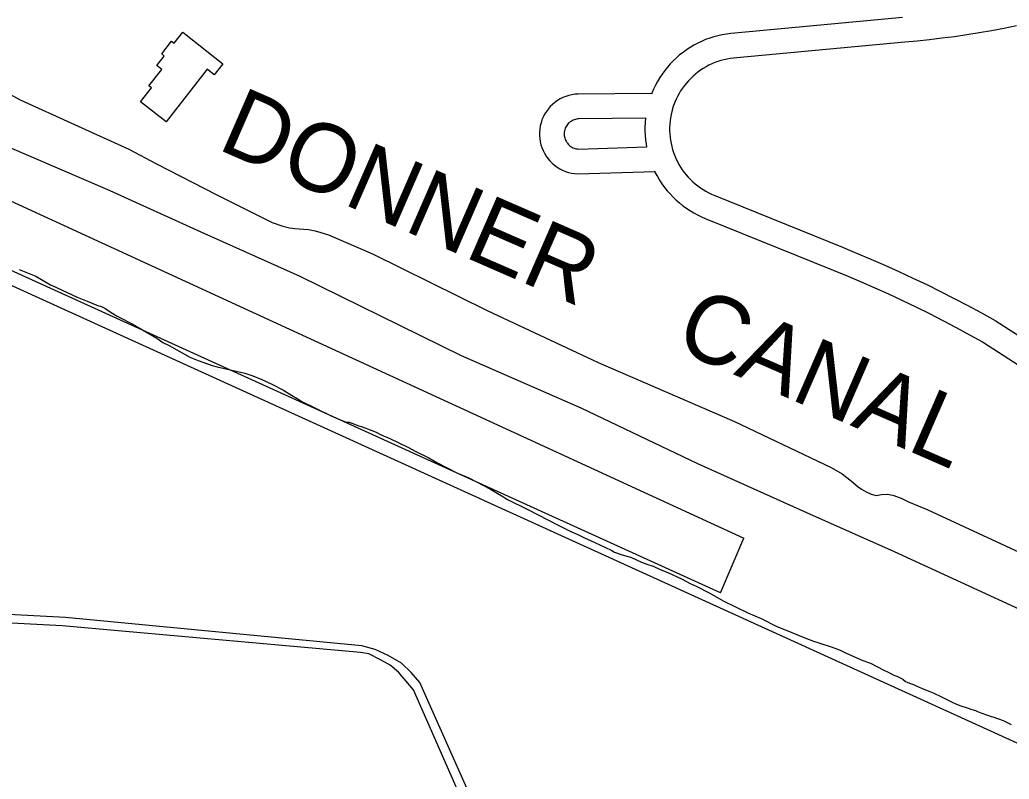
# Model space of a CAD drawing. Extents: x 3715084 to 3753216, y 488173 to 513963.
# Drawn here: x 3720571 to 3721771, y 509921 to 510842 of the extents above; entities that cross this region are included whole.
import ezdxf

# ---------------------------------------------------------------- set-up
doc = ezdxf.new("R2010")
doc.units = 0
for name, color, linetype in [('V-BLDG-OTLN', 7, 'Continuous'), ('V-LEVE-TOET', 7, 'Continuous'), ('V-RIVR-IDEN', 7, 'Continuous'), ('V-ROAD-CNTR', 7, 'Continuous'), ('V-SITE-VEGE', 7, 'Continuous'), ('V-TOPO-BNDY', 7, 'Continuous'), ('V-TOPO-SHOR', 7, 'Continuous')]:
    doc.layers.add(name, color=color, linetype=linetype)

msp = doc.modelspace()

# ---------------------------------------------------------------- linework, layer by layer
at = {"layer": 'V-BLDG-OTLN'}
msp.add_lwpolyline([(3720768.4, 510826.9), (3720817.2, 510788.8), (3720806.7, 510775.3), (3720798.2, 510782), (3720748.3, 510718.1), (3720717.2, 510742.4), (3720730.6, 510759.6), (3720727.4, 510762.1), (3720742.9, 510781.9), (3720736.9, 510786.5), (3720746, 510798.1), (3720742.9, 510800.6), (3720754.9, 510816), (3720758, 510813.6)], close=True, dxfattribs=at)
at = {"layer": 'V-LEVE-TOET'}
msp.add_line((3721421.2, 510147.1), (3721449.3, 510213.4), dxfattribs=at)
for points in [[(3719136.8, 511278.1), (3720138.4, 510815.9), (3721449.3, 510213.4)], [(3721421.2, 510147.1), (3719137.9, 511184.1)]]:
    msp.add_lwpolyline(points, dxfattribs=at)
at = {"layer": 'V-ROAD-CNTR'}
for points in [[(3721641.9, 510844.8), (3721438.4, 510825.9), (3721433.5, 510825.5), (3721428.3, 510824.8), (3721423.2, 510823.9), (3721418, 510822.8), (3721413, 510821.4), (3721408, 510819.8), (3721403, 510818), (3721398.2, 510815.9), (3721393.5, 510813.7), (3721388.8, 510811.2), (3721384.3, 510808.5), (3721379.9, 510805.7), (3721375.7, 510802.6), (3721371.5, 510799.4), (3721367.6, 510795.9), (3721363.8, 510792.3), (3721360.1, 510788.5), (3721356.6, 510784.6), (3721353.4, 510780.5), (3721350.3, 510776.3), (3721347.3, 510771.9), (3721344.6, 510767.4), (3721342.1, 510762.8), (3721339.8, 510758), (3721337.8, 510753.2), (3721337.3, 510752)], [(3721780.3, 510834.6), (3721765, 510831.5), (3721750, 510828.7), (3721735, 510826.1), (3721720, 510823.7), (3721704.9, 510821.5), (3721689.9, 510819.6), (3721674.7, 510817.8), (3721659.6, 510816.3), (3721644.6, 510815), (3721441, 510796), (3721436.7, 510795.6), (3721432.9, 510795.1), (3721429, 510794.5), (3721425.2, 510793.6), (3721421.4, 510792.6), (3721417.7, 510791.4), (3721414.1, 510790.1), (3721410.5, 510788.5), (3721407, 510786.9), (3721403.5, 510785), (3721400.2, 510783.1), (3721396.9, 510780.9), (3721393.7, 510778.6), (3721390.7, 510776.2), (3721387.7, 510773.7), (3721384.9, 510771), (3721382.2, 510768.2), (3721379.6, 510765.3), (3721377.2, 510762.2), (3721374.9, 510759.1), (3721372.7, 510755.8), (3721370.7, 510752.5), (3721368.8, 510749.1), (3721367.1, 510745.6), (3721365.6, 510742), (3721364.2, 510738.3), (3721363, 510734.6), (3721362.7, 510733.7), (3721361.9, 510730.9), (3721361.1, 510727.1), (3721360.4, 510723.2), (3721359.8, 510719.4), (3721359.5, 510715.5), (3721359.3, 510711.6), (3721359.3, 510707.7), (3721359.4, 510703.8), (3721359.8, 510699.9), (3721360.3, 510696), (3721361, 510692.2), (3721361.9, 510688.4), (3721362.9, 510684.6), (3721364.1, 510680.9), (3721364.9, 510678.7), (3721365.5, 510677.3), (3721367, 510673.7), (3721368.7, 510670.2), (3721370.5, 510666.7), (3721372.5, 510663.4), (3721374.7, 510660.1), (3721377, 510657), (3721379.4, 510653.9), (3721382, 510651), (3721384.7, 510648.2), (3721387.5, 510645.5), (3721390.4, 510642.9), (3721393.5, 510640.5), (3721396.6, 510638.2), (3721399.9, 510636.1), (3721403.2, 510634.1), (3721406.7, 510632.2), (3721410.2, 510630.5), (3721414, 510628.9), (3721569.1, 510566.2), (3721586.3, 510559.1), (3721603.5, 510551.9), (3721620.6, 510544.4), (3721637.6, 510536.7), (3721654.6, 510528.8), (3721671.4, 510520.8), (3721688.2, 510512.5), (3721704.8, 510504), (3721721.3, 510495.3), (3721737.8, 510486.4), (3721754.4, 510477.1), (3721825.5, 510431.5)], [(3721337.6, 510752.7), (3721248.2, 510751.9), (3721244.5, 510751.7), (3721240.7, 510751.1), (3721237, 510750.3), (3721233.4, 510749.2), (3721229.8, 510747.7), (3721226.4, 510746), (3721223.2, 510744.1), (3721220.1, 510741.8), (3721217.1, 510739.4), (3721214.4, 510736.7), (3721211.9, 510733.8), (3721209.7, 510730.8), (3721207.6, 510727.5), (3721205.9, 510724.1), (3721204.4, 510720.6), (3721203.2, 510717), (3721202.3, 510713.3), (3721201.7, 510709.5), (3721201.3, 510705.8), (3721201.3, 510701.9), (3721201.6, 510698.1), (3721202.2, 510694.4), (3721203.1, 510690.6), (3721204.2, 510687), (3721205.7, 510683.5), (3721207.4, 510680.1), (3721209.4, 510676.8), (3721211.6, 510673.7), (3721214.1, 510670.8), (3721216.8, 510668.1), (3721219.7, 510665.6), (3721222.7, 510663.4), (3721226, 510661.4), (3721229.4, 510659.7), (3721232.9, 510658.2), (3721236.6, 510657), (3721240.3, 510656.1), (3721244, 510655.5), (3721248.1, 510655.2), (3721341.2, 510658.2)], [(3721330, 510722.6), (3721249.3, 510722), (3721247.7, 510721.8), (3721246.3, 510721.6), (3721244.9, 510721.3), (3721243.5, 510720.9), (3721242.2, 510720.3), (3721240.9, 510719.7), (3721239.6, 510718.9), (3721238.4, 510718.1), (3721237.3, 510717.2), (3721236.3, 510716.2), (3721235.4, 510715.1), (3721234.5, 510713.9), (3721233.7, 510712.7), (3721233.1, 510711.4), (3721232.5, 510710.1), (3721232, 510708.7), (3721231.7, 510707.3), (3721231.5, 510705.8), (3721231.3, 510704.4), (3721231.3, 510703), (3721231.4, 510701.5), (3721231.7, 510700.1), (3721232, 510698.7), (3721232.4, 510697.3), (3721233, 510696), (3721233.6, 510694.7), (3721234.4, 510693.4), (3721235.2, 510692.3), (3721236.2, 510691.2), (3721237.2, 510690.1), (3721238.3, 510689.2), (3721239.5, 510688.3), (3721240.7, 510687.6), (3721242, 510686.9), (3721243.3, 510686.4), (3721244.7, 510685.9), (3721246.1, 510685.6), (3721247.5, 510685.4), (3721248.7, 510685.3), (3721331.3, 510687.9)], [(3721330.1, 510723.3), (3721330, 510722.8), (3721329.5, 510717.6), (3721329.3, 510712.3), (3721329.3, 510707.1), (3721329.5, 510701.8), (3721330, 510696.6), (3721330.7, 510691.4), (3721331.4, 510687.6)], [(3721340.8, 510658.8), (3721341.9, 510656.6), (3721344.4, 510652), (3721347.1, 510647.4), (3721350, 510643.1), (3721353.1, 510638.8), (3721356.4, 510634.7), (3721359.8, 510630.8), (3721363.5, 510627), (3721367.2, 510623.3), (3721371.2, 510619.9), (3721375.3, 510616.6), (3721379.6, 510613.5), (3721383.9, 510610.6), (3721388.5, 510608), (3721393.1, 510605.5), (3721397.8, 510603.2), (3721402.5, 510601.2), (3721557.8, 510538.4), (3721574.8, 510531.4), (3721591.7, 510524.3), (3721608.5, 510517), (3721625.1, 510509.5), (3721641.8, 510501.7), (3721658.3, 510493.8), (3721674.7, 510485.7), (3721691, 510477.3), (3721707.2, 510468.8), (3721723.3, 510460.1), (3721739, 510451.4), (3721808.8, 510406.6)]]:
    msp.add_lwpolyline(points, dxfattribs=at)
at = {"layer": 'V-SITE-VEGE'}
for p, q in [((3720569.8, 510539.2), (3720589.9, 510530.9)), ((3720589.9, 510530.9), (3720607.8, 510520.5)), ((3720607.8, 510520.5), (3720614.3, 510517.8)), ((3720614.3, 510517.8), (3720621.9, 510513.9)), ((3720621.9, 510513.9), (3720640.3, 510505.7)), ((3720640.3, 510505.7), (3720652.2, 510500.7)), ((3720652.2, 510500.7), (3720666.3, 510495.2)), ((3720666.3, 510495.2), (3720668.5, 510494.7)), ((3720668.5, 510494.7), (3720671.2, 510493.6)), ((3720671.2, 510493.6), (3720675, 510491.4)), ((3720675, 510491.4), (3720681.5, 510487)), ((3720681.5, 510487), (3720688.6, 510482.6)), ((3720688.6, 510482.6), (3720694.5, 510479.8)), ((3720694.5, 510479.8), (3720703.7, 510474.9)), ((3720703.7, 510474.9), (3720707, 510473.3)), ((3720707, 510473.3), (3720736.8, 510455.7)), ((3720736.8, 510455.7), (3720744.4, 510450.8)), ((3720744.4, 510450.8), (3720752, 510446.9)), ((3720752, 510446.9), (3720776.9, 510432.7)), ((3720776.9, 510432.7), (3720787.2, 510428.8)), ((3720787.2, 510428.8), (3720804, 510422.7)), ((3720804, 510422.7), (3720810, 510421.1)), ((3720810, 510421.1), (3720827.9, 510417.2)), ((3720827.9, 510417.2), (3720843.6, 510413.3)), ((3720843.6, 510413.3), (3720852.3, 510410.5)), ((3720852.3, 510410.5), (3720863.7, 510406.1)), ((3720863.7, 510406.1), (3720876.7, 510400.1)), ((3720876.7, 510400.1), (3720890.8, 510392.9)), ((3720890.8, 510392.9), (3720898.4, 510388)), ((3720898.4, 510388), (3720909.2, 510381.4)), ((3720909.2, 510381.4), (3720913, 510379.2)), ((3720913, 510379.2), (3720947.7, 510362.2)), ((3720947.7, 510362.2), (3720955.8, 510358.4)), ((3720955.8, 510358.4), (3720966.7, 510353.9)), ((3720966.7, 510353.9), (3720970.5, 510353.9)), ((3720970.5, 510353.9), (3720981.9, 510349.5)), ((3720981.9, 510349.5), (3720986.2, 510348.4)), ((3720986.2, 510348.4), (3720992.7, 510345.7)), ((3720992.7, 510345.7), (3721003, 510341.8)), ((3721003, 510341.8), (3721009, 510338.5)), ((3721009, 510338.5), (3721019.8, 510334.1)), ((3721019.8, 510334.1), (3721041.5, 510323.7)), ((3721041.5, 510323.7), (3721051.3, 510318.2)), ((3721051.3, 510318.2), (3721067, 510310.5)), ((3721067, 510310.5), (3721076.8, 510305)), ((3721076.8, 510305), (3721101.2, 510292.4)), ((3721101.2, 510292.4), (3721115.8, 510286.3)), ((3721115.8, 510286.3), (3721141.8, 510272.6)), ((3721141.8, 510272.6), (3721154.8, 510264.9)), ((3721154.8, 510264.9), (3721162.4, 510260)), ((3721162.4, 510260), (3721187.3, 510247.9)), ((3721187.3, 510247.9), (3721224.2, 510229.2)), ((3721224.2, 510229.2), (3721239.4, 510221.5)), ((3721239.4, 510221.5), (3721248.1, 510217.7)), ((3721248.1, 510217.7), (3721256.7, 510213.3)), ((3721256.7, 510213.3), (3721263.2, 510210.5)), ((3721263.2, 510210.5), (3721280.6, 510202.3)), ((3721280.6, 510202.3), (3721289.3, 510198.4)), ((3721289.3, 510198.4), (3721292.5, 510196.2)), ((3721292.5, 510196.2), (3721300.6, 510193.5)), ((3721300.6, 510193.5), (3721313.1, 510189.6)), ((3721313.1, 510189.6), (3721325, 510184.1)), ((3721325, 510184.1), (3721331.6, 510181.9)), ((3721331.6, 510181.9), (3721339.2, 510179.1)), ((3721339.2, 510179.1), (3721347.8, 510175.3)), ((3721347.8, 510175.3), (3721357, 510171.4)), ((3721357, 510171.4), (3721374.4, 510163.7)), ((3721374.4, 510163.7), (3721384.2, 510158.3)), ((3721384.2, 510158.3), (3721391.7, 510154.9)), ((3721391.7, 510154.9), (3721408, 510146.7)), ((3721408, 510146.7), (3721424.3, 510137.4)), ((3721424.3, 510137.4), (3721454.1, 510122.6)), ((3721454.1, 510122.6), (3721462.8, 510119.2)), ((3721462.8, 510119.2), (3721470.3, 510115.9)), ((3721470.3, 510115.9), (3721489.3, 510106.1)), ((3721489.3, 510106.1), (3721500.7, 510101.7)), ((3721500.7, 510101.7), (3721523.5, 510092.3)), ((3721523.5, 510092.3), (3721533.8, 510088.4)), ((3721533.8, 510088.4), (3721540.3, 510086.2)), ((3721540.3, 510086.2), (3721556.6, 510081.2)), ((3721556.6, 510081.2), (3721566.3, 510077.4)), ((3721566.3, 510077.4), (3721572.9, 510074.1)), ((3721572.9, 510074.1), (3721594, 510064.7)), ((3721594, 510064.7), (3721603.2, 510061.4)), ((3721603.2, 510061.4), (3721619.5, 510053.2)), ((3721619.5, 510053.2), (3721624.4, 510050.5)), ((3721624.4, 510050.5), (3721631.4, 510047.2)), ((3721631.4, 510047.2), (3721635.2, 510046)), ((3721635.2, 510046), (3721640.1, 510043.3)), ((3721640.1, 510043.3), (3721642.3, 510042.2)), ((3721642.3, 510042.2), (3721645.5, 510039.5)), ((3721645.5, 510039.5), (3721647.7, 510038.4)), ((3721647.7, 510038.4), (3721650.4, 510037.3)), ((3721650.4, 510037.3), (3721655.3, 510035.6)), ((3721655.3, 510035.6), (3721658.5, 510034)), ((3721658.5, 510034), (3721667.7, 510030.1)), ((3721667.7, 510030.1), (3721675.3, 510027.4)), ((3721675.3, 510027.4), (3721679.1, 510025.7)), ((3721679.1, 510025.7), (3721689.4, 510020.8)), ((3721689.4, 510020.8), (3721702.4, 510014.2)), ((3721702.4, 510014.2), (3721707.3, 510012)), ((3721707.3, 510012), (3721712.7, 510009.8)), ((3721712.7, 510009.8), (3721720.3, 510007.6)), ((3721720.3, 510007.6), (3721726.3, 510005.3)), ((3721726.3, 510005.3), (3721730.6, 510004.2)), ((3721730.6, 510004.2), (3721732.8, 510003.1)), ((3721732.8, 510003.1), (3721737.1, 510001.5)), ((3721737.1, 510001.5), (3721746.4, 509998.2)), ((3721746.4, 509998.2), (3721749.6, 509997.1)), ((3721749.6, 509997.1), (3721751.8, 509996.5)), ((3721751.8, 509996.5), (3721764.3, 509992.1)), ((3721764.3, 509992.1), (3721774, 509987.2))]:
    msp.add_line(p, q, dxfattribs=at)
at = {"layer": 'V-TOPO-BNDY'}
msp.add_line((3719138.1, 511166.3), (3723819.3, 509038.5), dxfattribs=at)
at = {"layer": 'V-TOPO-SHOR'}
for points in [[(3720162.2, 510863.9), (3720242.4, 510830.4), (3720293.2, 510808.7), (3720379.4, 510769.1), (3720522.4, 510702.5), (3720679.8, 510635.2), (3720790.3, 510584.7), (3720910.5, 510531.1), (3721106.2, 510434.7), (3721251.4, 510371.2), (3721393.2, 510303.8), (3721525.5, 510244.2), (3721631.8, 510196.9), (3721793.7, 510122.6), (3721924.2, 510061.5), (3722079, 509993.5), (3722202.3, 509940.6), (3722405.5, 509845.5)], [(3720544.9, 510759), (3720571.2, 510744.9), (3720703.1, 510685.2), (3720736.6, 510667.5), (3720809.9, 510629.6)], [(3720809.9, 510629.6), (3720876.9, 510596.2), (3720889.8, 510591.7), (3720898.1, 510589.8), (3720904.5, 510589), (3720909.7, 510588.5), (3720915.4, 510587.9), (3720921.1, 510587.7), (3720929.1, 510586.1), (3720935.8, 510584.2), (3720945.3, 510581.1), (3720998.5, 510558.1), (3721137.7, 510489.6), (3721272.6, 510426.4), (3721437.9, 510354.7), (3721555.2, 510299.1), (3721568.7, 510291.3), (3721580.2, 510282.4), (3721588.2, 510275.6), (3721592.1, 510272.5), (3721597.7, 510269.4), (3721603.9, 510266.5), (3721609.9, 510264.9), (3721616.3, 510266.2), (3721623.3, 510266.7), (3721630.3, 510265.4), (3721640.4, 510261.9), (3721649.4, 510257.2), (3721672.6, 510247.8), (3721828.1, 510175.7)], [(3721454.8, 509127.4), (3721394.1, 509274.1), (3721242.1, 509620), (3721056, 510038.1), (3721045.6, 510050.1), (3721033.7, 510061.4), (3721017.8, 510070.8), (3721002, 510078.2), (3720985.7, 510082.6), (3720626.1, 510116.9), (3720333.8, 510132.5)], [(3721447.8, 509120.5), (3721377.6, 509276.6), (3721229.7, 509617.1), (3721048.3, 510029.2), (3721030.1, 510050.8), (3721020, 510059.1), (3721008.3, 510065.7), (3720994.1, 510072.9), (3720984.1, 510074.7), (3720621.9, 510106.9), (3720321.9, 510122.5)]]:
    msp.add_lwpolyline(points, dxfattribs=at)

# ---------------------------------------------------------------- texts
at = {"layer": 'V-RIVR-IDEN'}
msp.add_text('DONNER    CANAL', height=83, rotation=336.4287, dxfattribs=at).set_placement((3720808.7, 510685.9))

doc.saveas('drawing.dxf')
